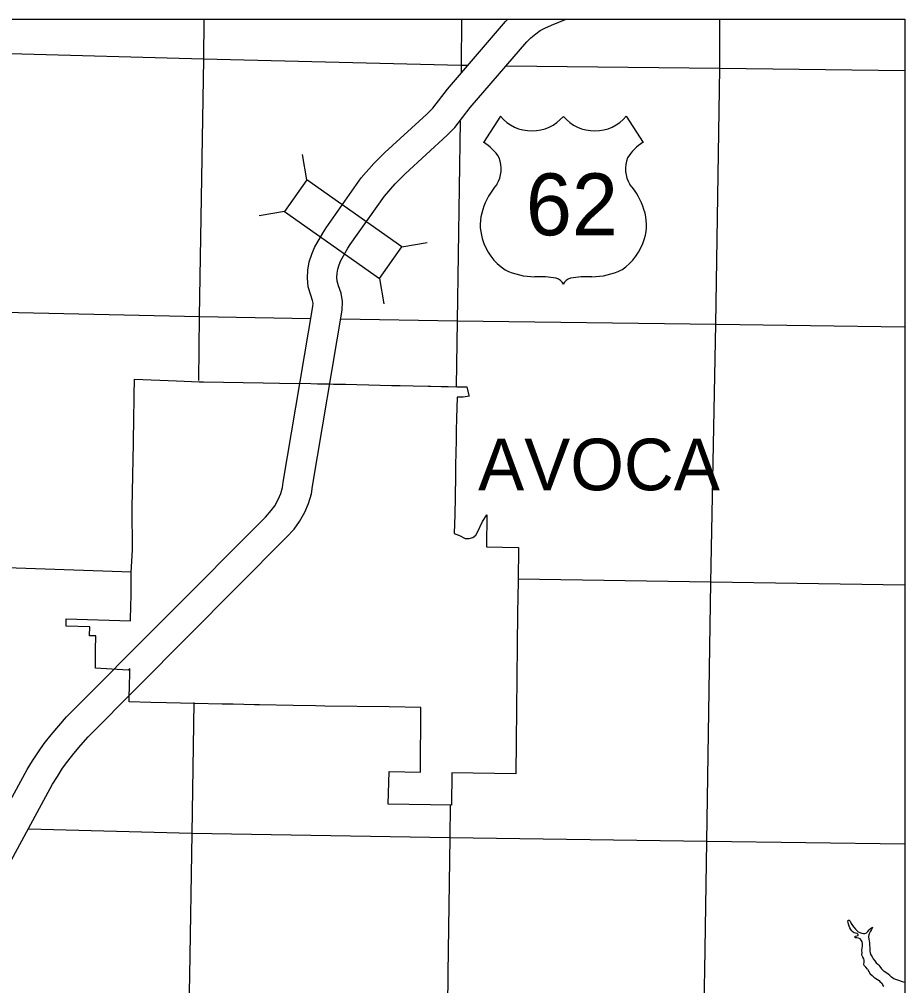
# Model space of a CAD drawing. Extents: x 309389.3 to 309420.2, y 336441.4 to 336461.2.
# Drawn here: x 309393.483 to 309394.854, y 336458.352 to 336459.85 of the extents above; entities that cross this region are included whole.
import ezdxf

# ---------------------------------------------------------------- set-up
doc = ezdxf.new("R2010")
doc.units = 0
for name, color, linetype in [('Level 2', 7, 'Continuous'), ('Level 37', 7, 'Continuous'), ('Level 4', 7, 'Continuous'), ('Level 62', 7, 'Continuous'), ('R_Axis Annot', 7, 'Continuous'), ('R_Detour Annot', 7, 'Continuous'), ('R_MOT', 7, 'Continuous')]:
    doc.layers.add(name, color=color, linetype=linetype)

msp = doc.modelspace()

# ---------------------------------------------------------------- linework, layer by layer
at = {"layer": 'Level 2'}
for points in [[(309394.7971, 336458.3777), (309394.7945, 336458.3806), (309394.792, 336458.3831), (309394.7914, 336458.3853), (309394.7915, 336458.3886), (309394.7915, 336458.3913), (309394.7913, 336458.3936), (309394.7899, 336458.3959), (309394.7889, 336458.3981), (309394.7882, 336458.4005), (309394.7884, 336458.4031), (309394.7883, 336458.4072), (309394.7888, 336458.4101), (309394.7892, 336458.4134), (309394.7893, 336458.4172), (309394.7887, 336458.4201), (309394.7873, 336458.4225), (309394.7853, 336458.4248), (309394.783, 336458.4258), (309394.7805, 336458.4261), (309394.7777, 336458.4261), (309394.7773, 336458.4279), (309394.7785, 336458.4288), (309394.7803, 336458.429), (309394.7826, 336458.4296), (309394.7822, 336458.4311), (309394.781, 336458.4326), (309394.7784, 336458.4335), (309394.7765, 336458.4341), (309394.7745, 336458.4351), (309394.7724, 336458.4368), (309394.7711, 336458.439), (309394.7694, 336458.4415), (309394.7685, 336458.444), (309394.7676, 336458.4472), (309394.767, 336458.4499), (309394.7665, 336458.4519), (309394.7669, 336458.4534), (309394.7683, 336458.4537), (309394.7701, 336458.4518), (309394.7715, 336458.4481), (309394.7735, 336458.4454), (309394.7759, 336458.4424), (309394.7784, 336458.4394), (309394.7807, 336458.4372), (309394.7827, 336458.4355), (309394.7852, 336458.4342), (309394.7881, 336458.4331), (309394.7905, 336458.4329), (309394.7928, 336458.433), (309394.7952, 336458.4341), (309394.7973, 336458.4361), (309394.7993, 336458.4384), (309394.8015, 336458.4404), (309394.8048, 336458.4425), (309394.8033, 336458.439), (309394.8014, 336458.4363), (309394.7993, 336458.4325), (309394.799, 336458.431), (309394.7986, 336458.4281), (309394.7988, 336458.4237), (309394.7994, 336458.4213), (309394.8002, 336458.4181), (309394.8001, 336458.4147), (309394.8004, 336458.4105), (309394.8005, 336458.4057), (309394.8009, 336458.4026), (309394.802, 336458.3996), (309394.804, 336458.3964), (309394.8058, 336458.3936), (309394.8083, 336458.3903), (309394.8104, 336458.3872), (309394.8129, 336458.3854), (309394.8146, 336458.3835), (309394.8162, 336458.3815), (309394.8187, 336458.3781)], [(309394.7971, 336458.3777), (309394.7992, 336458.3741), (309394.8009, 336458.3705), (309394.8041, 336458.3678), (309394.8065, 336458.3652), (309394.81, 336458.3633), (309394.8148, 336458.3601), (309394.8162, 336458.3586), (309394.8194, 336458.3551), (309394.8204, 336458.3536), (309394.8209, 336458.3524), (309394.822, 336458.351)], [(309394.8545, 336458.3569), (309394.851, 336458.3577), (309394.8454, 336458.3599), (309394.841, 336458.3614), (309394.8378, 336458.3626), (309394.8342, 336458.3652), (309394.8313, 336458.3679), (309394.8287, 336458.3698), (309394.8252, 336458.3724), (309394.8227, 336458.3741), (309394.8207, 336458.376), (309394.8187, 336458.3781)]]:
    msp.add_lwpolyline(points, dxfattribs=at)
at = {"layer": 'Level 37'}
for p, q in [((309393.9282, 336459.601), (309393.9214, 336459.6404)), ((309393.8937, 336459.5519), (309393.8543, 336459.5451)), ((309394.0754, 336459.4973), (309394.1148, 336459.5041)), ((309394.0408, 336459.4483), (309394.0477, 336459.4089))]:
    msp.add_line(p, q, dxfattribs=at)
msp.add_lwpolyline([(309394.0754, 336459.4973), (309393.9282, 336459.601), (309393.8937, 336459.5519), (309394.0408, 336459.4483)], close=True, dxfattribs=at)
at = {"layer": 'Level 4'}
for points in [[(309393.7607, 336459.2902), (309393.7621, 336459.3891), (309393.7688, 336459.7875), (309393.7689, 336459.8498)], [(309394.1678, 336459.8498), (309394.1674, 336459.7777), (309394.1672, 336459.7664)], [(309394.5447, 336458.3756), (309394.5481, 336458.5756), (309394.5542, 336458.9771), (309394.5617, 336459.3775), (309394.5683, 336459.7735), (309394.5682, 336459.8498)], [(309394.1781, 336459.7782), (309394.1671, 336459.7783), (309393.7683, 336459.7881), (309393.4679, 336459.7961)], [(309394.8545, 336459.7701), (309394.5679, 336459.7734), (309394.2372, 336459.7774)], [(309394.166, 336459.6921), (309394.1612, 336459.382), (309394.1593, 336459.281)], [(309393.0639, 336459.4049), (309393.3644, 336459.3978), (309393.7621, 336459.3891), (309393.9345, 336459.3862)], [(309393.9809, 336459.3854), (309394.1611, 336459.3825), (309394.5622, 336459.3774), (309394.8545, 336459.373)], [(309393.6565, 336458.9928), (309393.3584, 336459.0032), (309393.1011, 336459.0069)], [(309394.8545, 336458.9729), (309394.5544, 336458.9774), (309394.2557, 336458.9818)], [(309393.747, 336458.3678), (309393.7503, 336458.5878), (309393.7534, 336458.7907)], [(309394.1504, 336458.6315), (309394.1499, 336458.581), (309394.1465, 336458.3715)], [(309393.4967, 336458.5952), (309393.7501, 336458.5883), (309394.1497, 336458.5818), (309394.5481, 336458.5759), (309394.8545, 336458.5716)], [(309394.5381, 336457.8288), (309394.5409, 336458.1772), (309394.5447, 336458.3756)], [(309393.7371, 336457.7942), (309393.7433, 336458.1924), (309393.747, 336458.3678)], [(309394.1465, 336458.3715), (309394.1458, 336458.2649)]]:
    msp.add_lwpolyline(points, dxfattribs=at)
at = {"layer": 'Level 62'}
for points in [[(309393.6531, 336458.7921), (309393.6531, 336458.7939), (309393.6536, 336458.8214), (309393.6538, 336458.8315), (309393.6538, 336458.832), (309393.6538, 336458.8327), (309393.654, 336458.8438), (309393.6514, 336458.8411), (309393.6513, 336458.8411), (309393.6005, 336458.8443), (309393.6009, 336458.8718), (309393.6011, 336458.894), (309393.5915, 336458.8943), (309393.5917, 336458.908), (309393.5553, 336458.9093), (309393.5555, 336458.9206), (309393.6551, 336458.9172), (309393.6556, 336458.9421), (309393.6558, 336458.9549), (309393.6558, 336458.9926), (309393.6578, 336459.0277), (309393.6576, 336459.0924), (309393.6595, 336459.1928), (309393.6603, 336459.2335), (309393.6603, 336459.2352), (309393.6607, 336459.2568), (309393.6608, 336459.2669), (309393.6613, 336459.292), (309393.7263, 336459.2896), (309393.7613, 336459.2881), (309393.7682, 336459.2881), (309393.8604, 336459.2862), (309393.8856, 336459.2858), (309393.9346, 336459.2851), (309393.9449, 336459.285), (309393.9601, 336459.2848), (309393.962, 336459.2847), (309393.9697, 336459.2845), (309393.9882, 336459.2841), (309394.0054, 336459.2837), (309394.0243, 336459.2833), (309394.0591, 336459.2824), (309394.06, 336459.2824), (309394.0728, 336459.2822), (309394.0928, 336459.2817), (309394.1162, 336459.2813), (309394.1172, 336459.2813), (309394.1203, 336459.2812), (309394.1364, 336459.2809), (309394.1474, 336459.2807), (309394.1605, 336459.2804), (309394.1613, 336459.2804), (309394.1693, 336459.2803), (309394.1763, 336459.2802), (309394.1794, 336459.2666), (309394.1796, 336459.2659), (309394.1702, 336459.2642), (309394.1686, 336459.264), (309394.161, 336459.2641), (309394.1609, 336459.2627), (309394.1606, 336459.2484), (309394.1606, 336459.2483), (309394.1602, 336459.2313), (309394.1602, 336459.2299), (309394.1598, 336459.2133), (309394.1598, 336459.2119), (309394.1595, 336459.1953), (309394.1594, 336459.194), (309394.1592, 336459.1815), (309394.1587, 336459.1555), (309394.1584, 336459.1432), (309394.1578, 336459.1086), (309394.1573, 336459.0825), (309394.1567, 336459.0528), (309394.1647, 336459.0499), (309394.1736, 336459.0451), (309394.1795, 336459.0449), (309394.1856, 336459.0465), (309394.1901, 336459.0501), (309394.1928, 336459.0549), (309394.2001, 336459.0713), (309394.207, 336459.0815), (309394.2065, 336459.0319), (309394.2562, 336459.031), (309394.2554, 336458.9796), (309394.2548, 336458.9293), (309394.2543, 336458.8793), (309394.2532, 336458.7798), (309394.2526, 336458.7306), (309394.252, 336458.6801), (309394.1527, 336458.6819), (309394.1521, 336458.6318), (309394.0541, 336458.6333), (309394.0559, 336458.6837), (309394.1043, 336458.6829), (309394.1048, 336458.7829), (309394.0555, 336458.7839), (309393.9559, 336458.7853), (309393.9414, 336458.7856), (309393.907, 336458.7863)], [(309393.907, 336458.7863), (309393.8548, 336458.7873), (309393.8471, 336458.7875), (309393.8141, 336458.7881), (309393.81, 336458.7881), (309393.7968, 336458.7884), (309393.754, 336458.7891), (309393.7106, 336458.7904), (309393.6867, 336458.7911), (309393.6531, 336458.7921)]]:
    msp.add_lwpolyline(points, dxfattribs=at)
at = {"layer": 'R_Axis Annot'}
for points in [[(309393.3245, 336458.3739), (309393.4948, 336458.6869), (309393.5032, 336458.7006), (309393.5122, 336458.7144), (309393.5213, 336458.7273), (309393.5318, 336458.7406), (309393.5438, 336458.7546), (309393.556, 336458.7686), (309393.864, 336459.0783), (309393.8731, 336459.0883), (309393.8785, 336459.0958), (309393.8839, 336459.1057), (309393.8879, 336459.115), (309393.8906, 336459.124), (309393.8917, 336459.1326), (309393.9375, 336459.4045), (309393.9379, 336459.4101), (309393.9372, 336459.414), (309393.9343, 336459.4223), (309393.9302, 336459.435), (309393.9292, 336459.4488), (309393.9297, 336459.4609), (309393.9318, 336459.4737), (309393.9359, 336459.4858), (309393.9402, 336459.4959), (309393.9528, 336459.5186), (309393.9581, 336459.5265), (309394.0126, 336459.6039), (309394.0318, 336459.6261), (309394.0492, 336459.6433), (309394.1139, 336459.703), (309394.1232, 336459.7122), (309394.1462, 336459.7418), (309394.2361, 336459.8464), (309394.2396, 336459.8498)], [(309393.3645, 336458.3522), (309393.5343, 336458.6642), (309393.5416, 336458.6764), (309393.5498, 336458.6889), (309393.5577, 336458.7001), (309393.5669, 336458.7117), (309393.5782, 336458.7249), (309393.5893, 336458.7376), (309393.8969, 336459.047), (309393.9084, 336459.0596), (309393.917, 336459.0714), (309393.9249, 336459.0859), (309393.9307, 336459.0995), (309393.9352, 336459.1145), (309393.9367, 336459.126), (309393.9827, 336459.3992), (309393.9836, 336459.4124), (309393.9813, 336459.4255), (309393.9774, 336459.4368), (309393.9752, 336459.4437), (309393.9747, 336459.4496), (309393.975, 336459.4564), (309393.976, 336459.4627), (309393.9783, 336459.4695), (309393.9811, 336459.4759), (309393.9916, 336459.4949), (309393.9955, 336459.5008), (309394.0484, 336459.5759), (309394.065, 336459.595), (309394.0806, 336459.6104), (309394.1454, 336459.6701), (309394.1573, 336459.682), (309394.1814, 336459.713), (309394.2692, 336459.8151), (309394.2752, 336459.821), (309394.2829, 336459.8272), (309394.2898, 336459.8324), (309394.2967, 336459.8362), (309394.3073, 336459.8407), (309394.33, 336459.8498)]]:
    msp.add_lwpolyline(points, dxfattribs=at)
at = {"layer": 'R_Detour Annot'}
for p, q in [((309394.2282, 336459.6996), (309394.2019, 336459.6591)), ((309394.4231, 336459.6996), (309394.4494, 336459.6591))]:
    msp.add_line(p, q, dxfattribs=at)
for centre, radius, start, end in [((309394.277, 336459.7407), 0.0638, 220.075, 319.6701), ((309394.3743, 336459.7407), 0.0638, 220.3299, 319.925), ((309394.1677, 336459.6002), 0.0681, 30.7809, 59.9883), ((309394.4836, 336459.6002), 0.0681, 120.0117, 149.2191), ((309394.1827, 336459.6182), 0.0467, 328.8105, 21.2108), ((309394.4686, 336459.6182), 0.0467, 158.7892, 211.1895), ((309394.3048, 336459.5224), 0.109, 138.9565, 162.6913), ((309394.3465, 336459.5224), 0.109, 17.3087, 41.0435), ((309394.2688, 336459.5314), 0.072, 160.9576, 197.3819), ((309394.3825, 336459.5314), 0.072, 342.6181, 19.0424), ((309394.2805, 336459.5316), 0.0833, 195.1074, 237.1312), ((309394.3708, 336459.5316), 0.0833, 302.8688, 344.8926), ((309394.2821, 336459.5578), 0.107, 244.0771, 269.5779), ((309394.3692, 336459.5578), 0.107, 270.4221, 295.9229), ((309394.2846, 336459.2549), 0.196, 81.1942, 90.9539), ((309394.3091, 336459.4306), 0.0188, 28.0342, 72.9864), ((309394.3422, 336459.4306), 0.0188, 107.0136, 151.9658), ((309394.3667, 336459.2549), 0.196, 89.0461, 98.8058)]:
    msp.add_arc(centre, radius, start, end, dxfattribs=at)
at = {"layer": 'R_MOT'}
msp.add_lwpolyline([(309389.3351, 336459.8498), (309394.8545, 336459.8498), (309394.8545, 336455.3696), (309389.3351, 336455.3696)], close=True, dxfattribs=at)

# ---------------------------------------------------------------- texts
at = {"layer": 'Level 62'}
msp.add_text('AVOCA', height=0.08, dxfattribs=at).set_placement((309394.1936, 336459.1198))
at = {"layer": 'R_Detour Annot'}
msp.add_text('62', height=0.096, dxfattribs=at).set_placement((309394.2675, 336459.515))

doc.saveas('drawing.dxf')
